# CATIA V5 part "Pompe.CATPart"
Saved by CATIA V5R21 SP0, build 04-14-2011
Part number: Pompe
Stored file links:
  C:\Users\zerma\Pictures\CAO\Pompe.CATPart
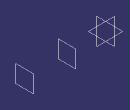
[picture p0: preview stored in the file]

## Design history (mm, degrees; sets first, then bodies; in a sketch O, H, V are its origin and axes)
Body1 (main body)
  Sketch1 on yz-plane, origin (0, 0, 0), H (0, 1, 0), V (0, 0, 1)
    line L1 (0, 0) -> (61, 0)
    point P1 (61, 0)
    line L2 (7.5844, 60) -> (60.5844, 60)
    point P2 (7.5844, 60)
    point P3 (60.5844, 60)
    spline S1 through (0, 0) (10, 30) (7.5844, 60)
    spline S2 through (61, 0) (70, 30) (60.5844, 60)
    point P4 (0, 0)
    point P5 (7.5844, 60)
    point P6 (61, 0)
    point P7 (60.5844, 60)
    length L1 = 61
    length L2 = 53
    distance L2 L1 = 60
    horizontal: L1 H, L2 H
    coincidence: P4 O, P5 P2, P6 P1, P7 P3
  Pad1: profile Sketch1, direction (1, 0, 0), length 42
  Sketch2 on face of Pad1 from Sketch1.L2, origin (0, 0, 60), H (1, 0, 0), V (0, 1, 0)
    circle A1 centre (20, 20) radius 6
    circle A2 centre (20, 20) radius 5.5
    radius A2 = 5.5
    radius A1 = 6
  Pad2: profile Sketch2, direction (0, 0, 1), length 13
  Plane1: type Offset, RefPlane yz-plane, Offset 20
  Sketch3 on yz-plane, origin (0, 0, 0), H (0, 1, 0), V (0, 0, 1)
    spline S1 through (0, 0) (10, 30) (7.5844, 60)
    reference projected point E1 (7.5844, 60) from vertex [face of Pad1 from Sketch1.S1 | start face of Pad1 | face of Pad1 from Sketch1.L2]
    spline S2 through (0, 0) (8.8433, 28.8113) (7.5844, 60)
    point P1 (0, 0)
    point P2 (7.5844, 60)
    point P3 (0, 0)
    point P4 (7.5844, 60)
    point P5 (8.8433, 28.8113)
    distance P5 S1 = 1
    coincidence: P1 O, P2 E1, P3 O, P4 P2
  Sketch4 on Plane1, origin (20, 0, 0), H (0, 1, 0), V (0, 0, 1)
    spline S1 through (0, 0) (-0.0826, 29.3405) (7.5844, 60)
    reference projected line E1 (60.5844, 60) -> (7.5844, 60) from edge [face of Pad1 from Sketch1.L2 | end face of Pad1]
    reference projected point E2 (7.5844, 60) from edge [face of Pad1 from Sketch1.S1 | face of Pad1 from Sketch1.L2]
    spline S2 through (0, 0) (10, 30) (7.5844, 60)
    point P1 (0, 0)
    point P2 (7.5844, 60)
    point P3 (0, 0)
    point P4 (7.5844, 60)
    coincidence: P1 O, E1 P2, P2 E2, P3 O, P4 P2
  Loft1: solid, Sections (Sketch3; Sketch4)
  Plane2: type Offset, RefPlane Plane1, Offset 22
  Sketch5 on Plane2, origin (42, 0, 0), H (0, 1, 0), V (0, 0, 1)
    spline S1 through (0, 0) (10, 30) (7.5844, 60)
    reference projected point E1 (7.5844, 60) from vertex [face of Pad1 from Sketch1.S1 | end face of Pad1 | face of Pad1 from Sketch1.L2]
    spline S2 through (0, 0) (9, 30) (7.5844, 60)
    point P1 (0, 0)
    point P2 (7.5844, 60)
    point P3 (0, 0)
    point P4 (7.5844, 60)
    point P5 (9, 30)
    point P6 (10, 30)
    distance P5 P6 = 1
    coincidence: P1 O, P2 E1, P3 O, P4 P2
  Loft2: solid, Sections (Sketch5; Sketch4)
  Fillet1: radius 3, on edge [face of Pad1 | face of Loft1]; edge [face of Loft1 | face of Pad1 from Sketch1.L2]; edge [face of Pad1 from Sketch1.L2 | face of Loft2]; edge [face of Loft2 | face of Pad1]; edge [face of Pad1 | face of Pad1 from Sketch1.L2]; edge [face of Pad1 from Sketch1.L2 | face of Pad1]; edge [face of Pad1 from Sketch1.L2 | face of Pad1 from Sketch1.S2]; edge [face of Pad1 | face of Pad1 from Sketch1.S2]; edge [face of Pad1 from Sketch1.S2 | face of Pad1]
